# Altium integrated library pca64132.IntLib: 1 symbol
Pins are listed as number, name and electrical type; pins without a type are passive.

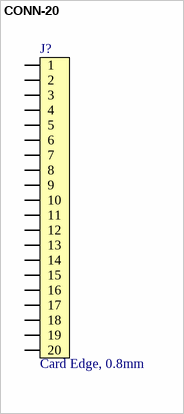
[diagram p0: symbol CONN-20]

## CONN-20
designator J?, comment Card Edge, 0.8mm
0.8mm pitch, dual edge, card edge connector; Part Number: 10056847-101LF Mating Board; Artikkelnr Noca: N.A.
footprint 10056847-101LF Mating Board
pins: 1, 2, 3, 4, 5, 6, 7, 8, 9, 10, 11, 12, 13, 14, 15, 16, 17, 18, 19, 20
